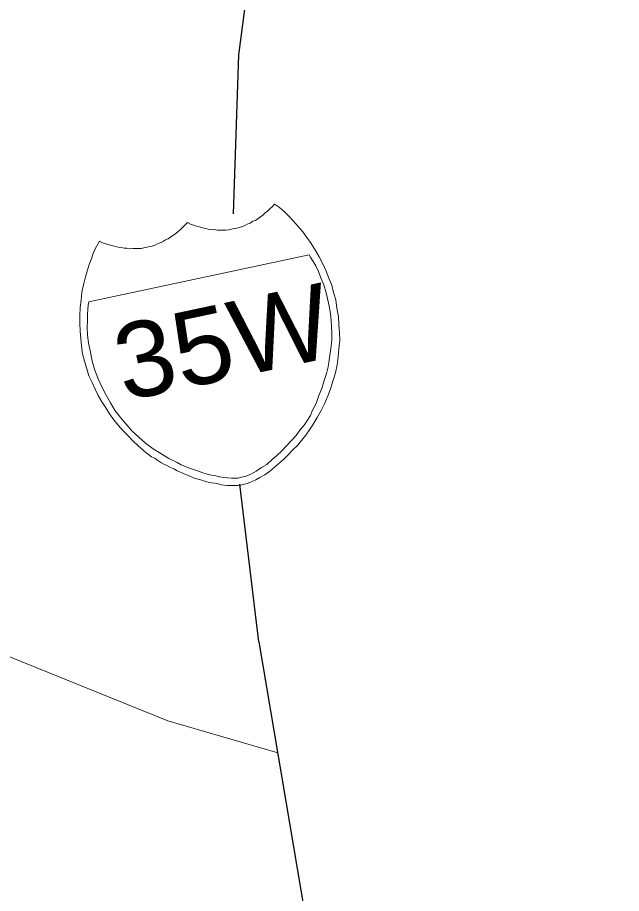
# Model space of a CAD drawing. Extents: x 2357218 to 2371708, y 6973728 to 6980157.
# Drawn here: x 2371385.2 to 2371426.1, y 6977700.8 to 6977760.1 of the extents above; entities that cross this region are included whole.
import ezdxf

# ---------------------------------------------------------------- set-up
doc = ezdxf.new("R2010")
doc.units = 0
doc.header["$LTSCALE"] = 2
doc.layers.add('62', color=7, linetype='Continuous', lineweight=13)
doc.layers.add('63', color=7, linetype='Continuous', lineweight=13)

msp = doc.modelspace()

# ---------------------------------------------------------------- linework, layer by layer
at = {"layer": '62', "lineweight": 25}
for p, q in [((2371400.159, 6977757.539), (2371399.803, 6977746.77)), ((2371401.542, 6977717.808), (2371400.241, 6977728.48))]:
    msp.add_line(p, q, dxfattribs=at)
for points in [[(2371426.054, 6977871.651), (2371425.57, 6977870.35), (2371420.887, 6977839.792), (2371411.556, 6977810.412), (2371404.442, 6977789.991), (2371400.159, 6977757.539)], [(2371401.542, 6977717.808), (2371409.053, 6977673.277), (2371413.016, 6977663.491)]]:
    msp.add_lwpolyline(points, dxfattribs=at)
at = {"layer": '62'}
for points in [[(2371397.528, 6977745.892), (2371397.729, 6977745.82), (2371397.945, 6977745.774), (2371398.112, 6977745.738), (2371398.329, 6977745.692), (2371398.53, 6977745.714), (2371398.725, 6977745.664), (2371398.906, 6977745.677), (2371399.113, 6977745.674), (2371399.299, 6977745.669), (2371399.503, 6977745.69), (2371399.679, 6977745.726), (2371399.876, 6977745.769), (2371400.052, 6977745.807), (2371400.228, 6977745.844), (2371400.443, 6977745.913), (2371400.588, 6977745.988), (2371400.755, 6977746.07), (2371400.949, 6977746.136), (2371401.128, 6977746.266), (2371401.302, 6977746.324), (2371401.481, 6977746.456), (2371401.643, 6977746.56), (2371401.8, 6977746.685), (2371401.955, 6977746.833), (2371402.112, 6977746.958), (2371402.284, 6977747.109), (2371402.458, 6977747.263), (2371402.606, 6977747.433), (2371402.932, 6977747.2), (2371403.246, 6977746.923), (2371403.562, 6977746.622), (2371403.889, 6977746.276), (2371404.192, 6977745.926), (2371404.502, 6977745.556), (2371404.788, 6977745.181), (2371405.086, 6977744.759), (2371405.37, 6977744.292), (2371405.62, 6977743.862), (2371405.859, 6977743.384), (2371406.078, 6977742.902), (2371406.274, 6977742.414), (2371406.465, 6977741.948), (2371406.594, 6977741.447), (2371406.746, 6977740.95), (2371406.819, 6977740.389), (2371406.914, 6977739.835), (2371406.943, 6977739.266), (2371406.984, 6977738.747), (2371407.008, 6977738.199), (2371406.944, 6977737.634), (2371406.9, 6977737.094), (2371406.831, 6977736.552), (2371406.713, 6977736.02), (2371406.57, 6977735.507), (2371406.402, 6977734.988), (2371406.232, 6977734.492), (2371405.999, 6977733.96), (2371405.758, 6977733.471), (2371405.49, 6977732.999), (2371405.185, 6977732.499), (2371404.959, 6977732.15), (2371404.711, 6977731.799), (2371404.42, 6977731.437), (2371404.143, 6977731.104), (2371403.821, 6977730.782), (2371403.503, 6977730.438), (2371403.198, 6977730.144), (2371402.888, 6977729.87), (2371402.578, 6977729.597), (2371402.263, 6977729.347), (2371401.946, 6977729.118), (2371401.615, 6977728.933), (2371401.325, 6977728.778), (2371401.031, 6977728.647), (2371400.738, 6977728.517), (2371400.474, 6977728.459)], [(2371400.474, 6977728.459), (2371400.298, 6977728.422), (2371400.143, 6977728.391), (2371399.96, 6977728.397), (2371399.799, 6977728.386), (2371399.613, 6977728.393), (2371399.428, 6977728.399), (2371399.195, 6977728.417), (2371398.983, 6977728.443), (2371398.786, 6977728.493), (2371398.57, 6977728.539), (2371398.332, 6977728.581), (2371398.114, 6977728.626), (2371397.874, 6977728.69), (2371397.672, 6977728.762), (2371397.428, 6977728.826), (2371397.187, 6977728.889), (2371396.96, 6977728.978), (2371396.708, 6977729.086), (2371396.48, 6977729.176), (2371396.25, 6977729.287), (2371396.023, 6977729.376), (2371395.786, 6977729.509), (2371395.559, 6977729.601), (2371395.351, 6977729.717), (2371395.12, 6977729.83), (2371394.912, 6977729.945), (2371394.698, 6977730.084), (2371394.508, 6977730.229), (2371394.276, 6977730.34), (2371394.084, 6977730.484), (2371393.92, 6977730.61), (2371393.724, 6977730.774), (2371393.384, 6977731.071), (2371393.015, 6977731.405), (2371392.685, 6977731.774), (2371392.359, 6977732.095), (2371392.029, 6977732.463), (2371391.724, 6977732.833), (2371391.431, 6977733.231), (2371391.182, 6977733.64), (2371390.913, 6977734.041), (2371390.681, 6977734.477), (2371390.474, 6977734.913), (2371390.266, 6977735.353), (2371390.054, 6977735.813), (2371389.906, 6977736.288), (2371389.75, 6977736.808), (2371389.619, 6977737.31), (2371389.556, 6977737.826), (2371389.494, 6977738.34), (2371389.457, 6977738.84), (2371389.436, 6977739.365), (2371389.438, 6977739.894), (2371389.464, 6977740.427), (2371389.52, 6977740.923), (2371389.565, 6977741.461), (2371389.688, 6977741.97), (2371389.794, 6977742.429), (2371389.929, 6977742.894), (2371390.063, 6977743.339), (2371390.244, 6977743.789), (2371390.368, 6977744.186), (2371390.56, 6977744.572), (2371390.763, 6977744.914), (2371390.969, 6977744.821), (2371391.19, 6977744.751), (2371391.411, 6977744.683), (2371391.606, 6977744.631), (2371391.827, 6977744.565), (2371392.022, 6977744.515), (2371392.234, 6977744.488), (2371392.428, 6977744.438), (2371392.609, 6977744.453), (2371392.805, 6977744.405), (2371393.008, 6977744.425), (2371393.193, 6977744.418), (2371393.422, 6977744.421), (2371393.583, 6977744.431), (2371393.759, 6977744.469), (2371393.978, 6977744.515), (2371394.152, 6977744.552), (2371394.33, 6977744.589), (2371394.525, 6977744.654), (2371394.69, 6977744.734), (2371394.856, 6977744.818), (2371395.028, 6977744.878), (2371395.232, 6977745.011), (2371395.402, 6977745.072), (2371395.559, 6977745.197), (2371395.721, 6977745.299), (2371395.9, 6977745.429), (2371396.074, 6977745.583), (2371396.231, 6977745.708), (2371396.386, 6977745.855), (2371396.537, 6977746.004), (2371396.708, 6977746.18), (2371396.912, 6977746.084), (2371397.11, 6977746.008), (2371397.333, 6977745.94), (2371397.528, 6977745.892)], [(2371351.534, 6977729.145), (2371352.418, 6977727.585), (2371359.856, 6977725.162), (2371369.31, 6977720.201), (2371383.434, 6977717.292), (2371395.384, 6977712.469), (2371402.815, 6977710.299)]]:
    msp.add_lwpolyline(points, dxfattribs=at)
msp.add_lwpolyline([(2371404.948, 6977743.994), (2371390.047, 6977740.828), (2371390.006, 6977740.588), (2371389.972, 6977740.307), (2371389.951, 6977739.978), (2371389.95, 6977739.542), (2371389.936, 6977739.078), (2371389.949, 6977738.576), (2371390.021, 6977738.017), (2371390.148, 6977737.42), (2371390.279, 6977736.804), (2371390.454, 6977736.199), (2371390.673, 6977735.602), (2371390.926, 6977735.057), (2371391.206, 6977734.497), (2371391.5, 6977733.984), (2371391.819, 6977733.453), (2371392.195, 6977732.981), (2371392.567, 6977732.529), (2371392.967, 6977732.063), (2371393.422, 6977731.655), (2371393.877, 6977731.244), (2371394.392, 6977730.871), (2371394.921, 6977730.545), (2371395.452, 6977730.223), (2371396.017, 6977729.951), (2371396.282, 6977729.779), (2371396.579, 6977729.68), (2371396.859, 6977729.556), (2371397.178, 6977729.461), (2371397.455, 6977729.359), (2371397.755, 6977729.24), (2371398.049, 6977729.164), (2371398.339, 6977729.088), (2371398.627, 6977729.033), (2371398.892, 6977728.976), (2371399.18, 6977728.922), (2371399.413, 6977728.902), (2371399.691, 6977728.892), (2371399.922, 6977728.894), (2371400.148, 6977728.897), (2371400.371, 6977728.944), (2371400.672, 6977729.032), (2371401.033, 6977729.177), (2371401.362, 6977729.364), (2371401.726, 6977729.601), (2371402.072, 6977729.813), (2371402.422, 6977730.116), (2371402.751, 6977730.417), (2371403.095, 6977730.743), (2371403.436, 6977731.092), (2371403.752, 6977731.434), (2371404.05, 6977731.773), (2371404.319, 6977732.131), (2371404.592, 6977732.465), (2371404.818, 6977732.812), (2371405.027, 6977733.13), (2371405.147, 6977733.431), (2371405.405, 6977733.948), (2371405.592, 6977734.471), (2371405.789, 6977734.952), (2371405.95, 6977735.49), (2371406.104, 6977735.96), (2371406.213, 6977736.42), (2371406.3, 6977736.876), (2371406.361, 6977737.349), (2371406.422, 6977737.82), (2371406.469, 6977738.245), (2371406.463, 6977738.704), (2371406.443, 6977739.137), (2371406.418, 6977739.57), (2371406.374, 6977739.997), (2371406.305, 6977740.419), (2371406.217, 6977740.836), (2371406.09, 6977741.43), (2371405.932, 6977741.973), (2371405.739, 6977742.437), (2371405.579, 6977742.863), (2371405.381, 6977743.258), (2371405.205, 6977743.545), (2371405.061, 6977743.79)], close=True, dxfattribs=at)
at = {"layer": '63', "lineweight": 25}
for p, q in [((2371400.159, 6977757.539), (2371399.803, 6977746.77)), ((2371401.542, 6977717.808), (2371400.241, 6977728.48))]:
    msp.add_line(p, q, dxfattribs=at)
for points in [[(2371426.054, 6977871.651), (2371425.57, 6977870.35), (2371420.887, 6977839.792), (2371411.556, 6977810.412), (2371404.442, 6977789.991), (2371400.159, 6977757.539)], [(2371401.542, 6977717.808), (2371409.053, 6977673.277), (2371413.016, 6977663.491)]]:
    msp.add_lwpolyline(points, dxfattribs=at)
at = {"layer": '63'}
for points in [[(2371397.528, 6977745.892), (2371397.729, 6977745.82), (2371397.945, 6977745.774), (2371398.112, 6977745.738), (2371398.329, 6977745.692), (2371398.53, 6977745.714), (2371398.725, 6977745.664), (2371398.906, 6977745.677), (2371399.113, 6977745.674), (2371399.299, 6977745.669), (2371399.503, 6977745.69), (2371399.679, 6977745.726), (2371399.876, 6977745.769), (2371400.052, 6977745.807), (2371400.228, 6977745.844), (2371400.443, 6977745.913), (2371400.588, 6977745.988), (2371400.755, 6977746.07), (2371400.949, 6977746.136), (2371401.128, 6977746.266), (2371401.302, 6977746.324), (2371401.481, 6977746.456), (2371401.643, 6977746.56), (2371401.8, 6977746.685), (2371401.955, 6977746.833), (2371402.112, 6977746.958), (2371402.284, 6977747.109), (2371402.458, 6977747.263), (2371402.606, 6977747.433), (2371402.932, 6977747.2), (2371403.246, 6977746.923), (2371403.562, 6977746.622), (2371403.889, 6977746.276), (2371404.192, 6977745.926), (2371404.502, 6977745.556), (2371404.788, 6977745.181), (2371405.086, 6977744.759), (2371405.37, 6977744.292), (2371405.62, 6977743.862), (2371405.859, 6977743.384), (2371406.078, 6977742.902), (2371406.274, 6977742.414), (2371406.465, 6977741.948), (2371406.594, 6977741.447), (2371406.746, 6977740.95), (2371406.819, 6977740.389), (2371406.914, 6977739.835), (2371406.943, 6977739.266), (2371406.984, 6977738.747), (2371407.008, 6977738.199), (2371406.944, 6977737.634), (2371406.9, 6977737.094), (2371406.831, 6977736.552), (2371406.713, 6977736.02), (2371406.57, 6977735.507), (2371406.402, 6977734.988), (2371406.232, 6977734.492), (2371405.999, 6977733.96), (2371405.758, 6977733.471), (2371405.49, 6977732.999), (2371405.185, 6977732.499), (2371404.959, 6977732.15), (2371404.711, 6977731.799), (2371404.42, 6977731.437), (2371404.143, 6977731.104), (2371403.821, 6977730.782), (2371403.503, 6977730.438), (2371403.198, 6977730.144), (2371402.888, 6977729.87), (2371402.578, 6977729.597), (2371402.263, 6977729.347), (2371401.946, 6977729.118), (2371401.615, 6977728.933), (2371401.325, 6977728.778), (2371401.031, 6977728.647), (2371400.738, 6977728.517), (2371400.474, 6977728.459)], [(2371400.474, 6977728.459), (2371400.298, 6977728.422), (2371400.143, 6977728.391), (2371399.96, 6977728.397), (2371399.799, 6977728.386), (2371399.613, 6977728.393), (2371399.428, 6977728.399), (2371399.195, 6977728.417), (2371398.983, 6977728.443), (2371398.786, 6977728.493), (2371398.57, 6977728.539), (2371398.332, 6977728.581), (2371398.114, 6977728.626), (2371397.874, 6977728.69), (2371397.672, 6977728.762), (2371397.428, 6977728.826), (2371397.187, 6977728.889), (2371396.96, 6977728.978), (2371396.708, 6977729.086), (2371396.48, 6977729.176), (2371396.25, 6977729.287), (2371396.023, 6977729.376), (2371395.786, 6977729.509), (2371395.559, 6977729.601), (2371395.351, 6977729.717), (2371395.12, 6977729.83), (2371394.912, 6977729.945), (2371394.698, 6977730.084), (2371394.508, 6977730.229), (2371394.276, 6977730.34), (2371394.084, 6977730.484), (2371393.92, 6977730.61), (2371393.724, 6977730.774), (2371393.384, 6977731.071), (2371393.015, 6977731.405), (2371392.685, 6977731.774), (2371392.359, 6977732.095), (2371392.029, 6977732.463), (2371391.724, 6977732.833), (2371391.431, 6977733.231), (2371391.182, 6977733.64), (2371390.913, 6977734.041), (2371390.681, 6977734.477), (2371390.474, 6977734.913), (2371390.266, 6977735.353), (2371390.054, 6977735.813), (2371389.906, 6977736.288), (2371389.75, 6977736.808), (2371389.619, 6977737.31), (2371389.556, 6977737.826), (2371389.494, 6977738.34), (2371389.457, 6977738.84), (2371389.436, 6977739.365), (2371389.438, 6977739.894), (2371389.464, 6977740.427), (2371389.52, 6977740.923), (2371389.565, 6977741.461), (2371389.688, 6977741.97), (2371389.794, 6977742.429), (2371389.929, 6977742.894), (2371390.063, 6977743.339), (2371390.244, 6977743.789), (2371390.368, 6977744.186), (2371390.56, 6977744.572), (2371390.763, 6977744.914), (2371390.969, 6977744.821), (2371391.19, 6977744.751), (2371391.411, 6977744.683), (2371391.606, 6977744.631), (2371391.827, 6977744.565), (2371392.022, 6977744.515), (2371392.234, 6977744.488), (2371392.428, 6977744.438), (2371392.609, 6977744.453), (2371392.805, 6977744.405), (2371393.008, 6977744.425), (2371393.193, 6977744.418), (2371393.422, 6977744.421), (2371393.583, 6977744.431), (2371393.759, 6977744.469), (2371393.978, 6977744.515), (2371394.152, 6977744.552), (2371394.33, 6977744.589), (2371394.525, 6977744.654), (2371394.69, 6977744.734), (2371394.856, 6977744.818), (2371395.028, 6977744.878), (2371395.232, 6977745.011), (2371395.402, 6977745.072), (2371395.559, 6977745.197), (2371395.721, 6977745.299), (2371395.9, 6977745.429), (2371396.074, 6977745.583), (2371396.231, 6977745.708), (2371396.386, 6977745.855), (2371396.537, 6977746.004), (2371396.708, 6977746.18), (2371396.912, 6977746.084), (2371397.11, 6977746.008), (2371397.333, 6977745.94), (2371397.528, 6977745.892)], [(2371351.534, 6977729.145), (2371352.418, 6977727.585), (2371359.856, 6977725.162), (2371369.31, 6977720.201), (2371383.434, 6977717.292), (2371395.384, 6977712.469), (2371402.815, 6977710.299)]]:
    msp.add_lwpolyline(points, dxfattribs=at)
msp.add_lwpolyline([(2371404.948, 6977743.994), (2371390.047, 6977740.828), (2371390.006, 6977740.588), (2371389.972, 6977740.307), (2371389.951, 6977739.978), (2371389.95, 6977739.542), (2371389.936, 6977739.078), (2371389.949, 6977738.576), (2371390.021, 6977738.017), (2371390.148, 6977737.42), (2371390.279, 6977736.804), (2371390.454, 6977736.199), (2371390.673, 6977735.602), (2371390.926, 6977735.057), (2371391.206, 6977734.497), (2371391.5, 6977733.984), (2371391.819, 6977733.453), (2371392.195, 6977732.981), (2371392.567, 6977732.529), (2371392.967, 6977732.063), (2371393.422, 6977731.655), (2371393.877, 6977731.244), (2371394.392, 6977730.871), (2371394.921, 6977730.545), (2371395.452, 6977730.223), (2371396.017, 6977729.951), (2371396.282, 6977729.779), (2371396.579, 6977729.68), (2371396.859, 6977729.556), (2371397.178, 6977729.461), (2371397.455, 6977729.359), (2371397.755, 6977729.24), (2371398.049, 6977729.164), (2371398.339, 6977729.088), (2371398.627, 6977729.033), (2371398.892, 6977728.976), (2371399.18, 6977728.922), (2371399.413, 6977728.902), (2371399.691, 6977728.892), (2371399.922, 6977728.894), (2371400.148, 6977728.897), (2371400.371, 6977728.944), (2371400.672, 6977729.032), (2371401.033, 6977729.177), (2371401.362, 6977729.364), (2371401.726, 6977729.601), (2371402.072, 6977729.813), (2371402.422, 6977730.116), (2371402.751, 6977730.417), (2371403.095, 6977730.743), (2371403.436, 6977731.092), (2371403.752, 6977731.434), (2371404.05, 6977731.773), (2371404.319, 6977732.131), (2371404.592, 6977732.465), (2371404.818, 6977732.812), (2371405.027, 6977733.13), (2371405.147, 6977733.431), (2371405.405, 6977733.948), (2371405.592, 6977734.471), (2371405.789, 6977734.952), (2371405.95, 6977735.49), (2371406.104, 6977735.96), (2371406.213, 6977736.42), (2371406.3, 6977736.876), (2371406.361, 6977737.349), (2371406.422, 6977737.82), (2371406.469, 6977738.245), (2371406.463, 6977738.704), (2371406.443, 6977739.137), (2371406.418, 6977739.57), (2371406.374, 6977739.997), (2371406.305, 6977740.419), (2371406.217, 6977740.836), (2371406.09, 6977741.43), (2371405.932, 6977741.973), (2371405.739, 6977742.437), (2371405.579, 6977742.863), (2371405.381, 6977743.258), (2371405.205, 6977743.545), (2371405.061, 6977743.79)], close=True, dxfattribs=at)

# ---------------------------------------------------------------- texts
at = {"layer": '62', "width": 1.05}
msp.add_text('35W', height=5.099, rotation=12, dxfattribs=at).set_placement((2371392.422, 6977734.088))
at = {"layer": '63', "width": 1.05}
msp.add_text('35W', height=5.099, rotation=12, dxfattribs=at).set_placement((2371392.422, 6977734.088))

doc.saveas('drawing.dxf')
